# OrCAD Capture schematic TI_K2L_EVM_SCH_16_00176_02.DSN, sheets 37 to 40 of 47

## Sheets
37 PAGE32 : K2L_POWER_SEQUENCING: size C; title: SOC Temp, UCD9090, PMBus Pgm conn, VID Isolator for PMBus
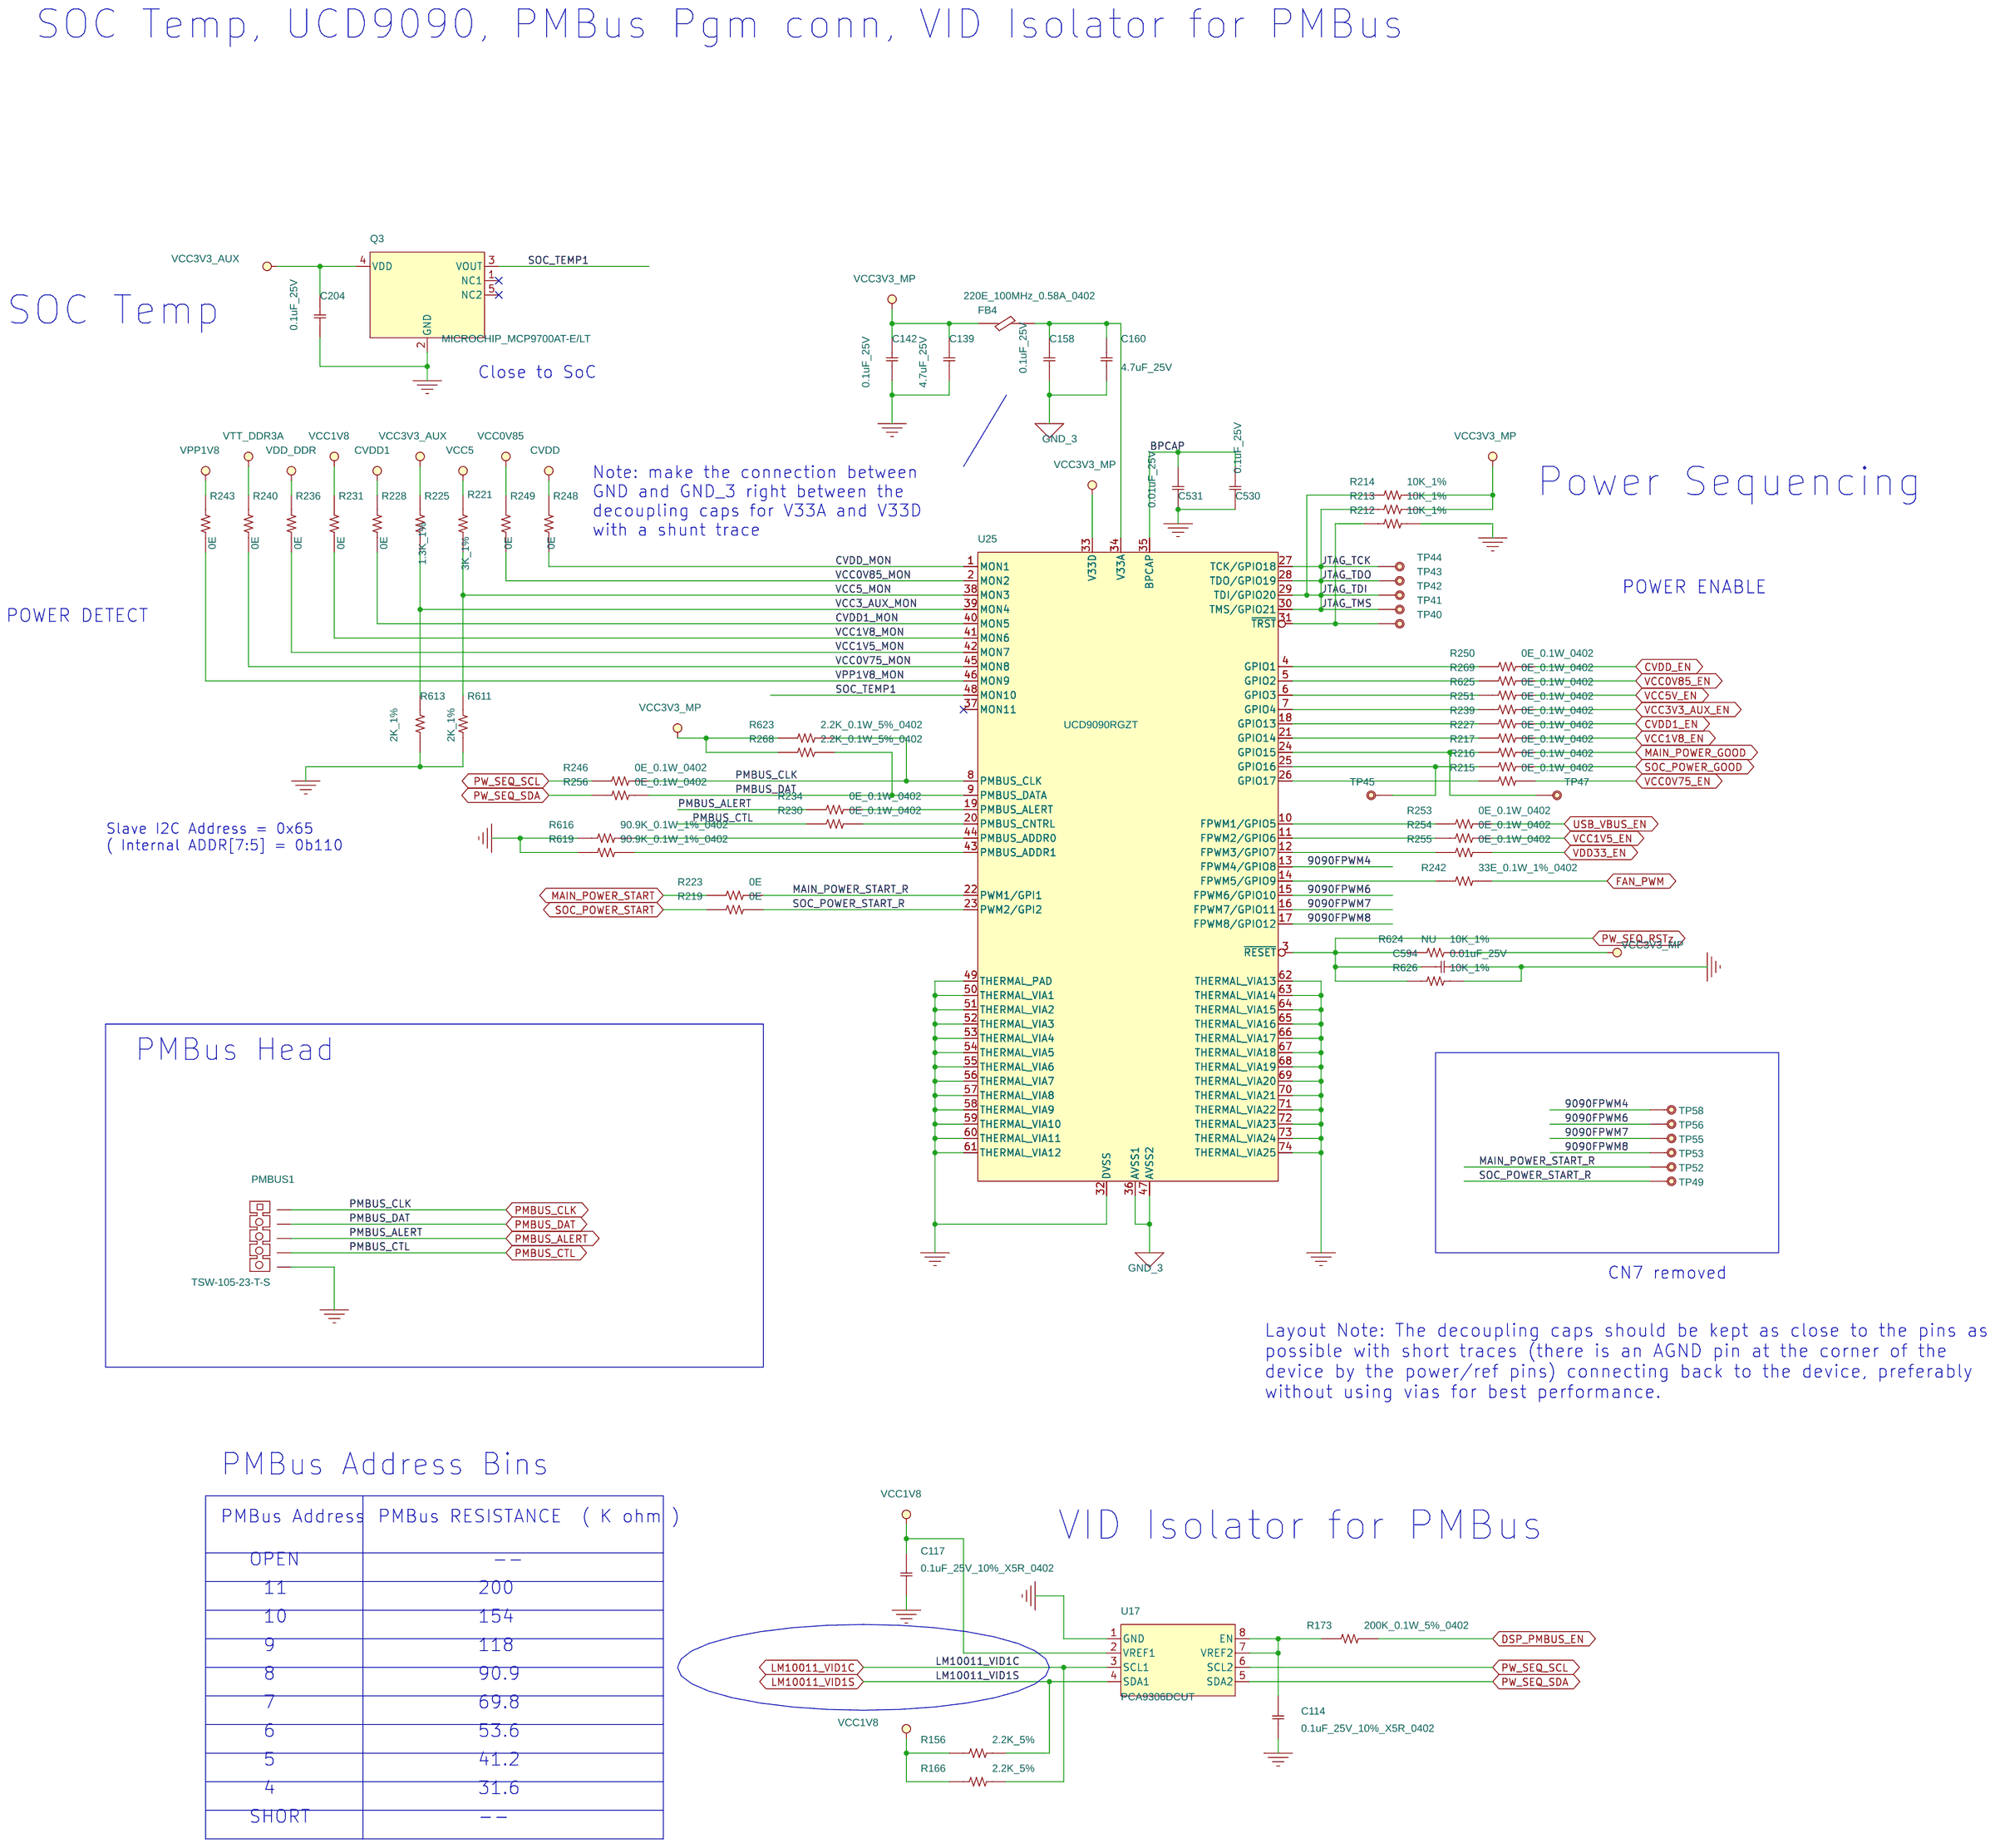
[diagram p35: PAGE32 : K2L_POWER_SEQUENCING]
38 PAGE08 : CLOCK DISTRIBUTION_C: title: CLOCK DISTRIBUTION
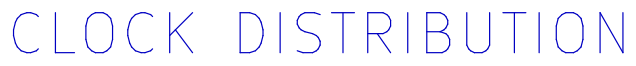
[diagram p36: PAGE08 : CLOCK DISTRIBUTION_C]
39 PAGE07 : POWER DISTRIBUTION_C: title: POWER DISTRIBUTION
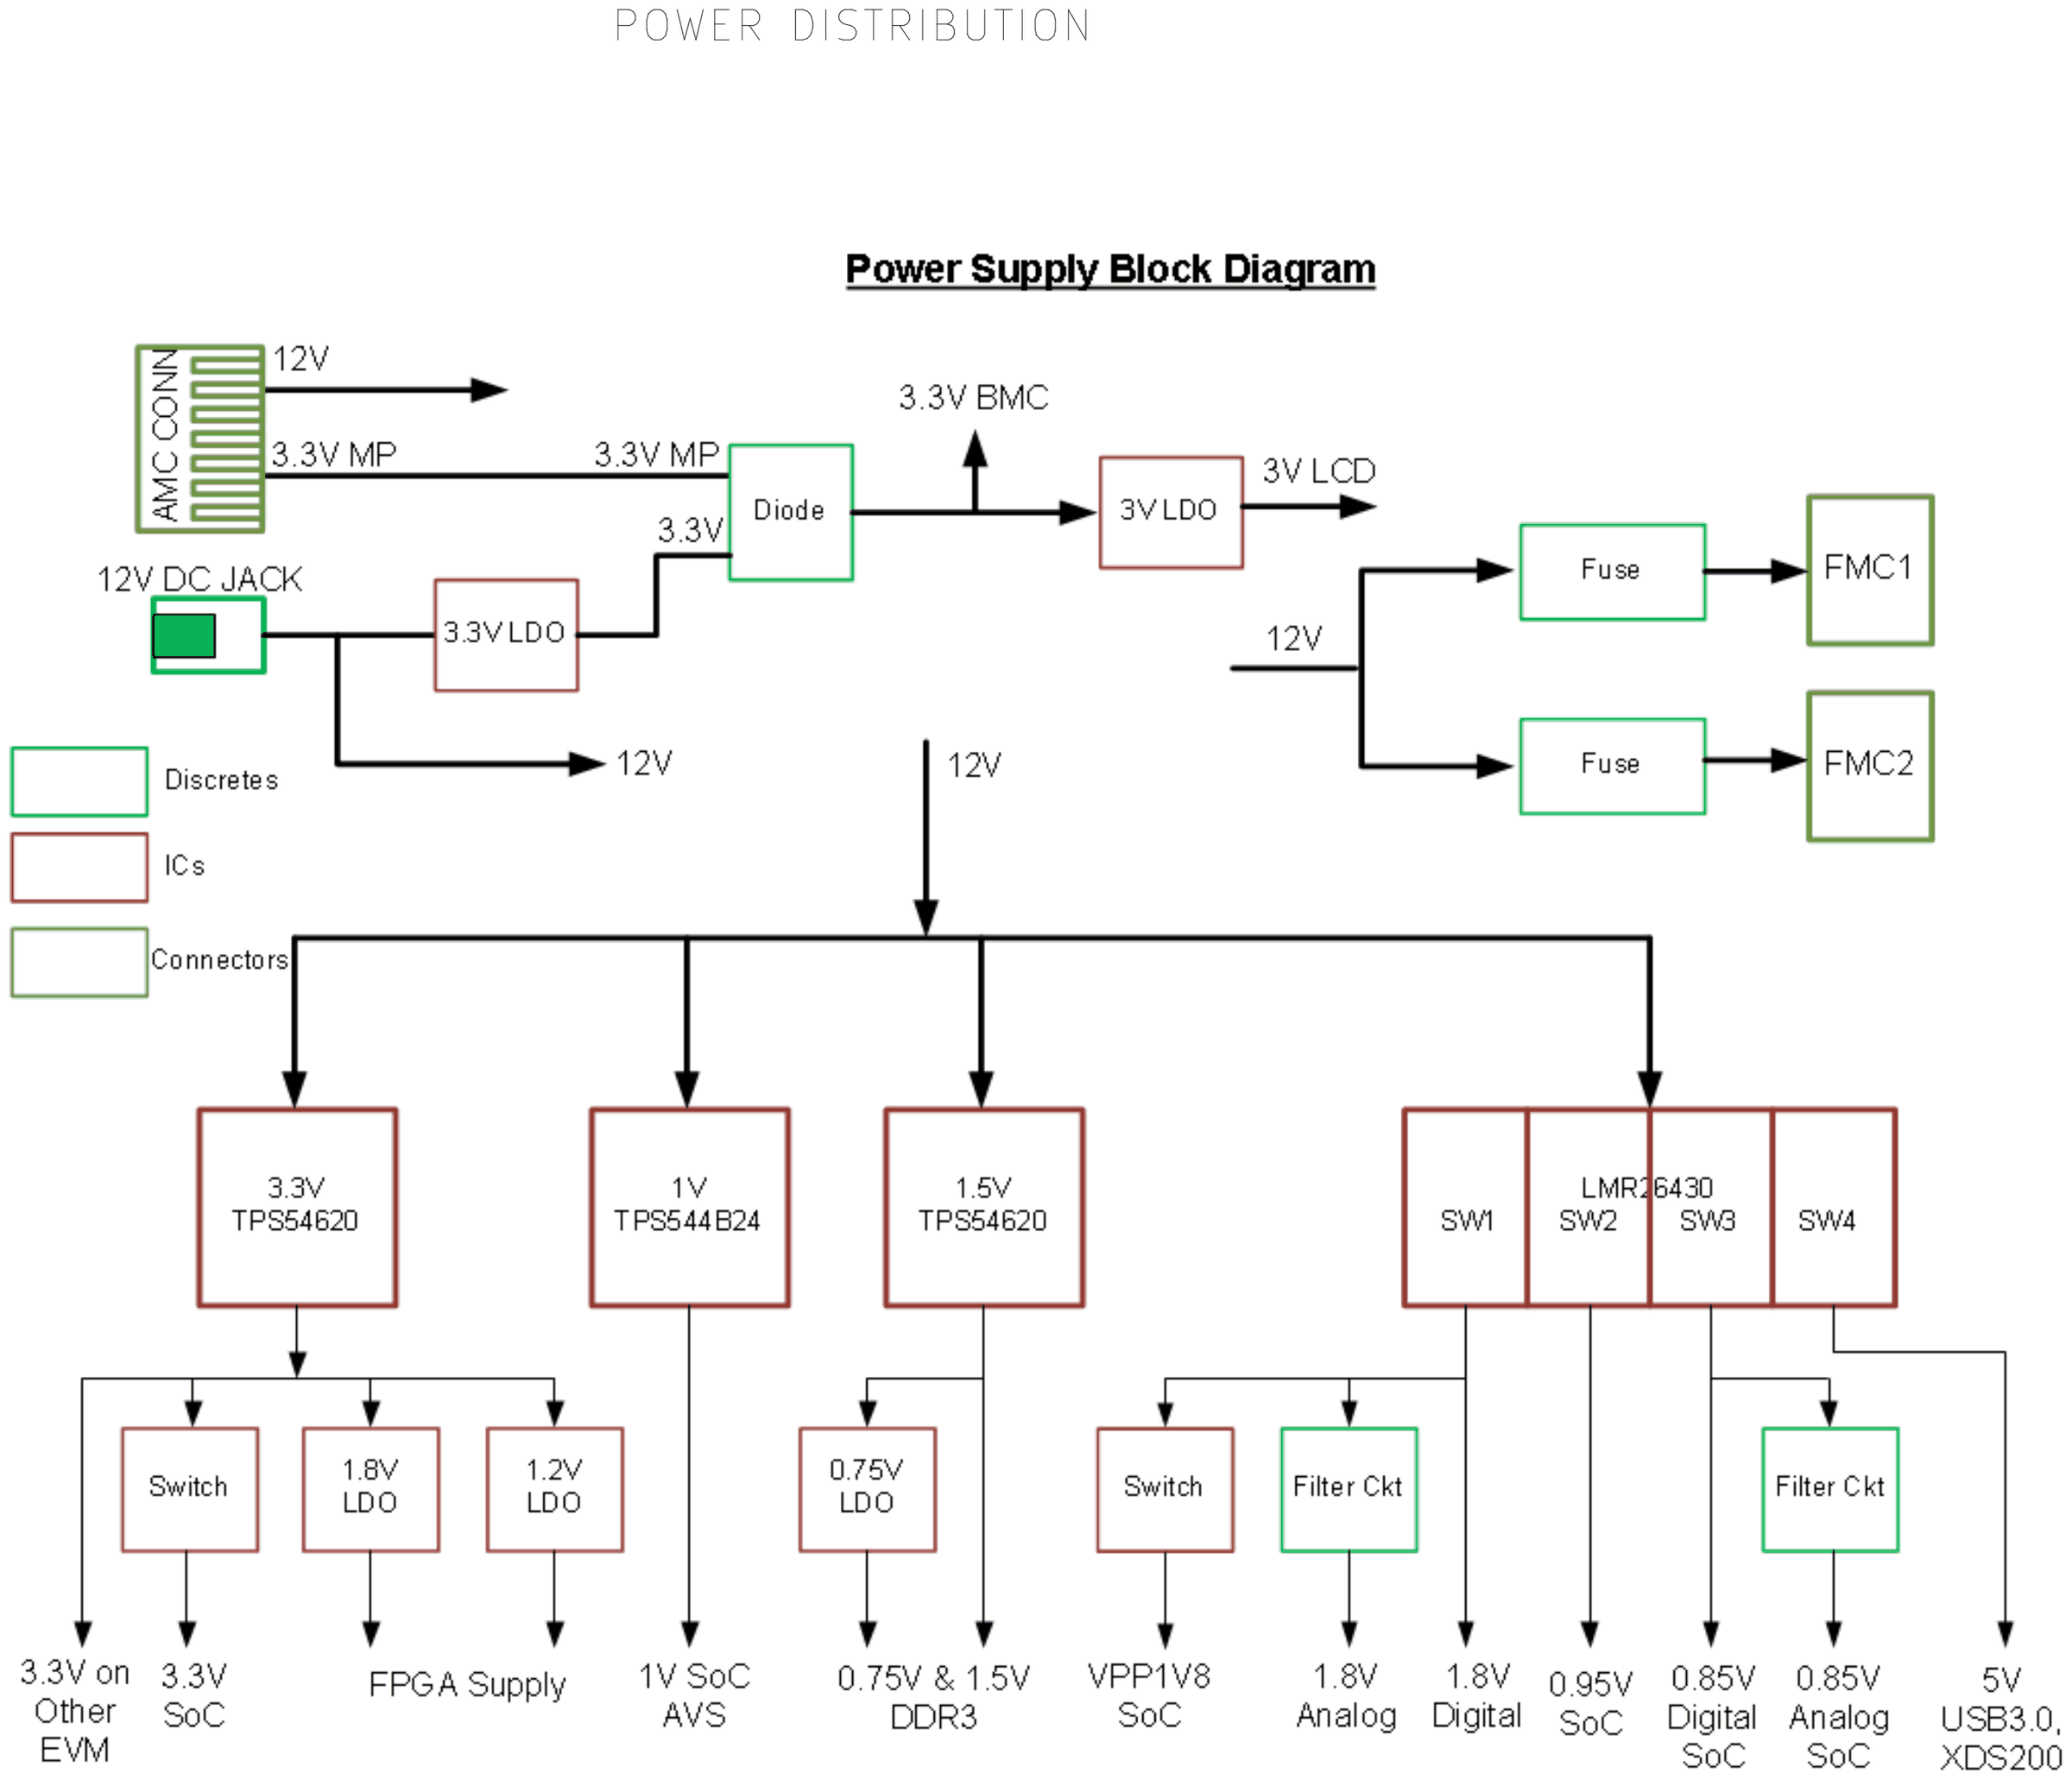
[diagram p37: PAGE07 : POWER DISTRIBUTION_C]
40 PAGE14 : SGMII/PCIe Serdes SW: size C; title: SGMII/PCIe Serdes switch
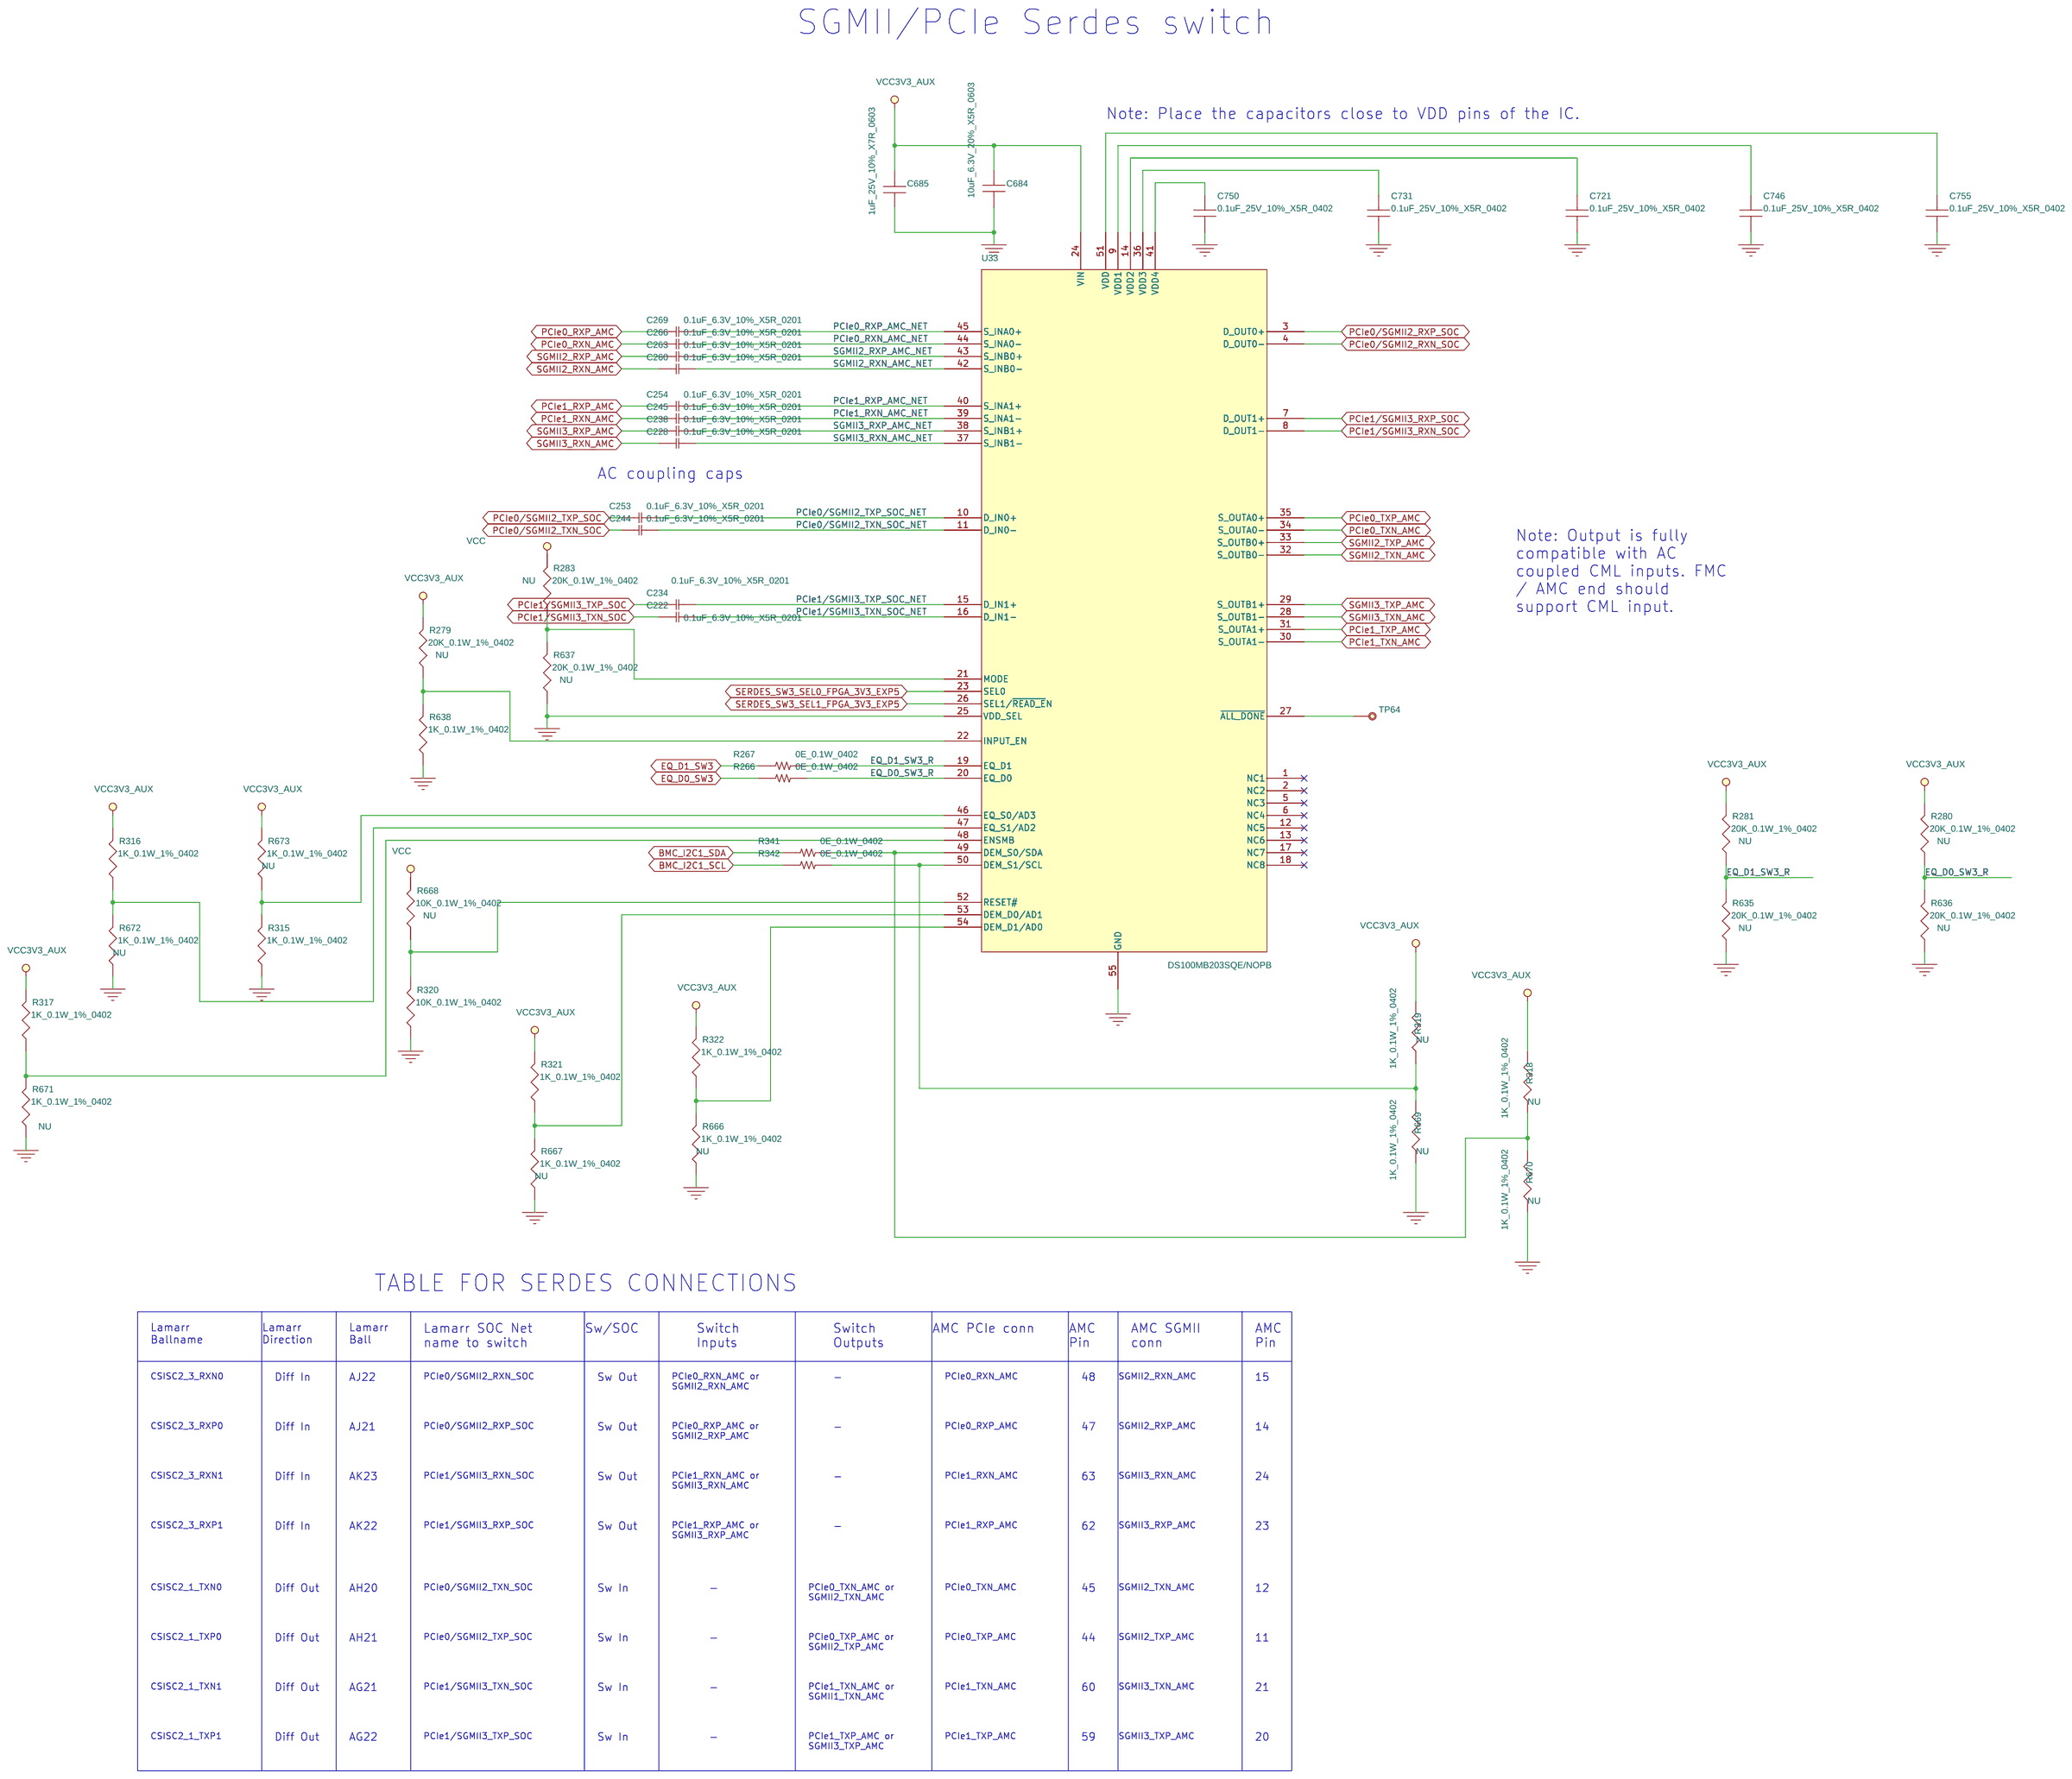
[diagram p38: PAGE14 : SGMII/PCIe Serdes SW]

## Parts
sheet PAGE14 : SGMII/PCIe Serdes SW
C222  0.1uF_6.3V_10%_X5R_0201  [CC0201]
C228  0.1uF_6.3V_10%_X5R_0201  [CC0201]
C234  0.1uF_6.3V_10%_X5R_0201  [CC0201]
C238  0.1uF_6.3V_10%_X5R_0201  [CC0201]
C244  0.1uF_6.3V_10%_X5R_0201  [CC0201]
C245  0.1uF_6.3V_10%_X5R_0201  [CC0201]
C253  0.1uF_6.3V_10%_X5R_0201  [CC0201]
C254  0.1uF_6.3V_10%_X5R_0201  [CC0201]
C260  0.1uF_6.3V_10%_X5R_0201  [CC0201]
C263  0.1uF_6.3V_10%_X5R_0201  [CC0201]
C266  0.1uF_6.3V_10%_X5R_0201  [CC0201]
C269  0.1uF_6.3V_10%_X5R_0201  [CC0201]
C684  10uF_6.3V_20%_X5R_0603  [C0603]
C685  1uF_25V_10%_X7R_0603  [C0603]
C721  0.1uF_25V_10%_X5R_0402  [C0402]
C731  0.1uF_25V_10%_X5R_0402  [C0402]
C746  0.1uF_25V_10%_X5R_0402  [C0402]
C750  0.1uF_25V_10%_X5R_0402  [C0402]
C755  0.1uF_25V_10%_X5R_0402  [C0402]
R266  0E_0.1W_0402  [R0402]
R267  0E_0.1W_0402  [R0402]
R279  20K_0.1W_1%_0402  [RC0402]
R280  20K_0.1W_1%_0402  [RC0402]
R281  20K_0.1W_1%_0402  [RC0402]
R283  20K_0.1W_1%_0402  [RC0402]
R315  1K_0.1W_1%_0402  [R0402]
R316  1K_0.1W_1%_0402  [R0402]
R317  1K_0.1W_1%_0402  [R0402]
R318  1K_0.1W_1%_0402  [R0402]
R319  1K_0.1W_1%_0402  [R0402]
R320  10K_0.1W_1%_0402  [R0402]
R321  1K_0.1W_1%_0402  [R0402]
R322  1K_0.1W_1%_0402  [R0402]
R341  0E_0.1W_0402  [R0402]
R342  0E_0.1W_0402  [R0402]
R635  20K_0.1W_1%_0402  [RC0402]
R636  20K_0.1W_1%_0402  [RC0402]
R637  20K_0.1W_1%_0402  [RC0402]
R638  1K_0.1W_1%_0402  [R0402]
R666  1K_0.1W_1%_0402  [R0402]
R667  1K_0.1W_1%_0402  [R0402]
R668  10K_0.1W_1%_0402  [R0402]
R669  1K_0.1W_1%_0402  [R0402]
R670  1K_0.1W_1%_0402  [R0402]
R671  1K_0.1W_1%_0402  [R0402]
R672  1K_0.1W_1%_0402  [R0402]
R673  1K_0.1W_1%_0402  [R0402]
TP64  TP  [TP-S40]
U33  DS100MB203SQE/NOPB  [QFN50P550X1000X80-55N_EINF]
sheet PAGE32 : K2L_POWER_SEQUENCING
C114  0.1uF_25V_10%_X5R_0402  [C0402]
C117  0.1uF_25V_10%_X5R_0402  [C0402]
C139  4.7uF_25V  [C0603]
C142  0.1uF_25V  [C0402]
C158  0.1uF_25V  [C0402]
C160  4.7uF_25V  [C0603]
C204  0.1uF_25V  [C0402]
C530  0.1uF_25V  [C0402]
C531  0.01uF_25V  [C0402]
C594  0.01uF_25V  [C0402]
FB4  220E_100MHz_0.58A_0402  [L0402]
PMBUS1  TSW-105-23-T-S  [HD_5x1P_100_D]
Q3  MICROCHIP_MCP9700AT-E/LT  [SC-70_5P]
R156  2.2K_5%  [R0402]
R166  2.2K_5%  [R0402]
R173  200K_0.1W_5%_0402  [R0402]
R212  10K_1%  [R0402]
R213  10K_1%  [R0402]
R214  10K_1%  [R0402]
R215  0E_0.1W_0402  [R0402]
R216  0E_0.1W_0402  [R0402]
R217  0E_0.1W_0402  [R0402]
R219  0E  [R0402]
R221  3K_1%  [R0402]
R223  0E  [R0402]
R225  1.3K_1%  [R0402]
R227  0E_0.1W_0402  [R0402]
R228  0E  [R0402]
R230  0E_0.1W_0402  [R0402]
R231  0E  [R0402]
R234  0E_0.1W_0402  [R0402]
R236  0E  [R0402]
R239  0E_0.1W_0402  [R0402]
R240  0E  [R0402]
R242  33E_0.1W_1%_0402  [R0402]
R243  0E  [R0402]
R246  0E_0.1W_0402  [R0402]
R248  0E  [R0402]
R249  0E  [R0402]
R250  0E_0.1W_0402  [R0402]
R251  0E_0.1W_0402  [R0402]
R253  0E_0.1W_0402  [R0402]
R254  0E_0.1W_0402  [R0402]
R255  0E_0.1W_0402  [R0402]
R256  0E_0.1W_0402  [R0402]
R268  2.2K_0.1W_5%_0402  [R0402]
R269  0E_0.1W_0402  [R0402]
R611  2K_1%  [R0402]
R613  2K_1%  [R0402]
R616  90.9K_0.1W_1%_0402  [R0402]
R619  90.9K_0.1W_1%_0402  [R0402]
R623  2.2K_0.1W_5%_0402  [R0402]
R624  10K_1%  [R0402]
R625  0E_0.1W_0402  [R0402]
R626  10K_1%  [R0402]
TP40  TP  [TP-S40]
TP41  TP  [TP-S40]
TP42  TP  [TP-S40]
TP43  TP  [TP-S40]
TP44  TP  [TP-S40]
TP45  TP  [TP-S40]
TP47  TP  [TP-S40]
TP49  TP  [TP-S40]
TP52  TP  [TP-S40]
TP53  TP  [TP-S40]
TP55  TP  [TP-S40]
TP56  TP  [TP-S40]
TP58  TP  [TP-S40]
U17  PCA9306DCUT  [SOIC_8P_20_79X122]
U25  UCD9090RGZT  [QFN_48P_20_276x276_TP202V25]

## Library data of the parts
C222 C228 C234 C238 C244 C245 C253 C254 C260 C263 C266 C269 = 11_C_12: CAP CER 0.1UF 6.3V 10% X5R 0201; Alt Mfg: Taiyo Yuden; Alt Mfg Part#: TMK105BJ104KV-F; Characteristic: <Characteristic>; Distributor_name: DIGIKEY; Distributor_part_number: 445-1796-1-ND; EIC Part#: 03_00583_01; Manufacture: TDK Corporation; Manufacture Part Number: C0603X5R0J104K030BC; Manufacture(English): TDK Corporation; Manufacture_Part_Number: C0603X5R0J104K030BC; Manufacturer: TDK Corporation; Manufacturer_Part_No: C0603X5R0J104K030BC; Mfg: TDK Corporation; Mfg Part#: 03_00583_01; Mfr_name: TDK Corporation; Mfr_part_number: C0603X5R0J104K030BC; Oper. Temp. Range: -55°C ~ 85°C; Package: 0201; Price @ 1: 0.10000; Price @ 10K: 0.00675; Price @ 1K: 0.00810; ProcessType: SMT; RoHS: Yes; Tolerance: 10%; Vendor: DIGIKEY; Vendor Part#: 445-1796-2-ND; Vendor_Part_No: 445-1796-1-ND; Voltage: 6.3V; eI Part#: 03_00583_01
C684 = CAP: CAP CER 10UF 6.3V 20% X5R 0603; Distributor_name: DIGIKEY; Distributor_part_number: 587-3383-1-ND; EIC Part#: 03_00605_01; Manufacture: Taiyo Yuden; Manufacture Part Number: JMK107ABJ106MAHT; Manufacture(English): Taiyo Yuden; Manufacture_Part_Number: JMK107ABJ106MAHT; Manufacturer: Taiyo Yuden; Manufacturer_Part_No: JMK107ABJ106MAHT; Mfg: Taiyo Yuden; Mfg Part#: JMK107ABJ106MAHT; Mfr_name: Taiyo Yuden; Mfr_part_number: JMK107ABJ106MAHT; Price @ 1: 0.44000; Price @ 10K: 0.06105; Price @ 1K: 0.12650; Vendor: DIGIKEY; Vendor_Part_No: 587-3383-1-ND; eI Part#: 03_00605_01
C685 = CAP: CAP CER 1UF 25V 10% X5R 0603; Distributor_name: DIGIKEY; Distributor_part_number: 490-3897-1-ND; EIC Part#: 03_00161_02; Manufacture: Murata; Manufacture Part Number: GRM188R61E105KA12D; Manufacture(English): Murata; Manufacture_Part_Number: GRM188R71E105KA12D; Manufacturer: Murata; Manufacturer_Part_No: GRM188R61E105KA12D; Mfg: Murata; Mfg Part#: 03_00161_02; Mfr_name: Murata; Mfr_part_number: GRM188R61E105KA12D; Price @ 1: 0.38000; Price @ 10K: 0.07363; Price @ 1K: 0.09353; Vendor: DIGIKEY; Vendor_Part_No: 490-3897-1-ND; eI Part#: 03_00161_02
C721 C731 C746 C750 C755 = CAP: CAP CER 0.1UF 25V 10% X5R 0402; Distributor_name: DIGIKEY; Distributor_part_number: 445-4964-1-ND; EIC Part#: 03_00470_02; Manufacture: TDK Corporation; Manufacture Part Number: C1005X5R1E104K050BC; Manufacture(English): TDK Corporation; Manufacture_Part_Number: GRM155R61E104KA87D; Manufacturer: TDK Corporation; Manufacturer_Part_No: C1005X5R1E104K050BC; Mfg: Murata Electronics North America; Mfg Part#: 03_00470_02; Mfr_name: TDK Corporation; Mfr_part_number: C1005X5R1E104K050BC; Price @ 1: 0.10000; Price @ 1K: 0.00960; Vendor: DIGIKEY; Vendor Part#: 445-4964-1-ND; Vendor_Part_No: 445-4964-1-ND; eI Part#: 03_00470_02
R266 R267 R341 R342 = 10_R_0: RES 0.0 OHM 1/10W JUMP 0402 SMD; Distributor_name: DIGIKEY; Distributor_part_number: P0.0JCT-ND; EIC Part#: 02_00019_01; Manufacture: Panasonic - ECG; Manufacture Part Number: ERJ-2GE0R00X; Manufacture(English): Panasonic - ECG; Manufacture_Part_Number: ERJ-2GE0R00X; Manufacturer: Panasonic - ECG; Manufacturer_Part_No: ERJ-2GE0R00X; Mfg: PANASONIC ELECTRONIC COMPONENTS (VA); Mfg Part#: 02_00019_01; Mfr_name: Panasonic - ECG; Mfr_part_number: ERJ-2GE0R00X; Price @ 1: 0.05000; Price @ 10K: 0.00248; Price @ 1K: 0.00480; Vendor: DIGIKEY; Vendor_Part_No: P0.0JCT-ND; eI Part#: 02_00019_01
R279 = DISC_RESISTOR: RES 20.0K OHM 1/10W 1% 0402 SMD; Distributor_name: DIGIKEY; Distributor_part_number: P20.0KLCT-ND; EIC Part#: 02_00037_01; Manufacture: Panasonic - ECG; Manufacture Part Number: ERJ-2RKF2002X; Manufacture(English): Panasonic - ECG; Manufacture_Part_Number: ERJ-2RKF2002X; Manufacturer: Panasonic - ECG; Manufacturer_Part_No: ERJ-2RKF2002X; Mfg Part#: 02_00037_01; Mfr_name: Panasonic - ECG; Mfr_part_number: ERJ-2RKF2002X; Mounting Status: NU; Mounting_Status: NU; Price @ 1: 0.10000; Price @ 10K: 0.00347; Price @ 1K: 0.00672; Vendor: DIGIKEY; Vendor_Part_No: P20.0KLCT-ND; eI Part#: 02_00045_01
R280 = DISC_RESISTOR: RES 20.0K OHM 1/10W 1% 0402 SMD; Distributor_name: DIGIKEY; Distributor_part_number: P20.0KLCT-ND; EIC Part#: 02_00037_01; Manufacture: Panasonic - ECG; Manufacture Part Number: ERJ-2RKF2002X; Manufacture(English): Panasonic - ECG; Manufacture_Part_Number: ERJ-2RKF2002X; Manufacturer: Panasonic - ECG; Manufacturer_Part_No: ERJ-2RKF2002X; Mfg Part#: 02_00037_01; Mfr_name: Panasonic - ECG; Mfr_part_number: ERJ-2RKF2002X; Mounting Status: NU; Mounting_Status: NU; Price @ 1: 0.10000; Price @ 10K: 0.00347; Price @ 1K: 0.00672; Vendor: DIGIKEY; Vendor_Part_No: P20.0KLCT-ND; eI Part#: 02_00247_01
R281 R637 = DISC_RESISTOR: RES 20.0K OHM 1/10W 1% 0402 SMD; Distributor_name: DIGIKEY; Distributor_part_number: P20.0KLCT-ND; EIC Part#: 02_00037_01; Manufacture: Panasonic - ECG; Manufacture Part Number: ERJ-2RKF2002X; Manufacture(English): Panasonic - ECG; Manufacture_Part_Number: ERJ-2RKF2002X; Manufacturer: Panasonic - ECG; Manufacturer_Part_No: ERJ-2RKF2002X; Mfg Part#: 02_00037_01; Mfr_name: Panasonic - ECG; Mfr_part_number: ERJ-2RKF2002X; Mounting Status: NU; Mounting_Status: NU; Price @ 1: 0.10000; Price @ 10K: 0.00347; Price @ 1K: 0.00672; Vendor: DIGIKEY; Vendor_Part_No: P20.0KLCT-ND; eI Part#: 02_00019_01
R283 = DISC_RESISTOR: RES 20.0K OHM 1/10W 1% 0402 SMD; Distributor_name: DIGIKEY; Distributor_part_number: P20.0KLCT-ND; EIC Part#: 02_00037_01; Manufacture: Panasonic - ECG; Manufacture Part Number: ERJ-2RKF2002X; Manufacture(English): Panasonic - ECG; Manufacture_Part_Number: ERJ-2RKF2002X; Manufacturer: Panasonic - ECG; Manufacturer_Part_No: ERJ-2RKF2002X; Mfg Part#: 02_00037_01; Mfr_name: Panasonic - ECG; Mfr_part_number: ERJ-2RKF2002X; Mounting Status: NU; Mounting_Status: NU; Price @ 1: 0.10000; Price @ 10K: 0.00347; Price @ 1K: 0.00672; Vendor: DIGIKEY; Vendor_Part_No: P20.0KLCT-ND; eI Part#: 02_00037_01
R315-R317 R321 R322 R638 = DISC_RESISTOR: RES 1.00K OHM 1/10W 1% 0402 SMD; Distributor_name: DIGIKEY; Distributor_part_number: P1.00KLCT-ND; EIC Part#: 02_00045_01; Manufacture: Panasonic - ECG; Manufacture Part Number: ERJ-2RKF1001X; Manufacture(English): Panasonic - ECG; Manufacture_Part_Number: ERJ-2RKF1001X; Manufacturer: Panasonic - ECG; Manufacturer_Part_No: ERJ-2RKF1001X; Mfg Part#: 02_00045_01; Mfr_name: Panasonic - ECG; Mfr_part_number: ERJ-2RKF1001X; Price @ 1: 0.10000; Price @ 10K: 0.00347; Price @ 1K: 0.00672; Vendor: DIGIKEY; Vendor_Part_No: P1.00KLCT-ND; eI Part#: 02_00045_01
R318 R319 R669 R670 = RESISTOR: RES 1.00K OHM 1/10W 1% 0402 SMD; Distributor_name: DIGIKEY; Distributor_part_number: P1.00KLCT-ND; EI Part#: 02_00045_01; EIC Part#: 02_00045_01; Manufacture: Panasonic - ECG; Manufacture Part Number: ERJ-2RKF1001X; Manufacture(English): Panasonic - ECG; Manufacture_Part_Number: ERJ-2RKF1001X; Manufacturer: Panasonic - ECG; Manufacturer_Part_No: ERJ-2RKF1001X; Mfg Part#: 02_00045_01; Mfr_name: Panasonic - ECG; Mfr_part_number: ERJ-2RKF1001X; Mounting Status: NU; Mounting_Status: NU; Price @ 1: 0.10000; Price @ 10K: 0.00347; Price @ 1K: 0.00672; Vendor: DIGIKEY; Vendor_Part_No: P1.00KLCT-ND
R320 = DISC_RESISTOR: RES 10K OHM 1/10W 1% 0402 SMD; Distributor_name: DIGIKEY; Distributor_part_number: P10.0KLCT-ND; EIC Part#: 02_00027_01; Manufacture: Panasonic - ECG; Manufacture Part Number: ERJ-2RKF1002X; Manufacture(English): Panasonic - ECG; Manufacture_Part_Number: ERJ-2RKF1002X; Manufacturer: Panasonic - ECG; Manufacturer_Part_No: ERJ-2RKF1002X; Mfg Part#: 02_00027_01; Mfr_name: Panasonic - ECG; Mfr_part_number: ERJ-2RKF1002X; Package: 0402; Price @ 1: 0.10000; Price @ 10K: 0.00347; Price @ 1K: 0.00672; Vendor: DIGIKEY; Vendor_Part_No: P10.0KLCT-ND; eI Part#: 02_00027_01
R635 = DISC_RESISTOR: RES 20.0K OHM 1/10W 1% 0402 SMD; Distributor_name: DIGIKEY; Distributor_part_number: P20.0KLCT-ND; EIC Part#: 02_00037_01; Manufacture: Panasonic - ECG; Manufacture Part Number: ERJ-2RKF2002X; Manufacture(English): Panasonic - ECG; Manufacture_Part_Number: ERJ-2RKF2002X; Manufacturer: Panasonic - ECG; Manufacturer_Part_No: ERJ-2RKF2002X; Mfg Part#: 02_00037_01; Mfr_name: Panasonic - ECG; Mfr_part_number: ERJ-2RKF2002X; Mounting Status: NU; Mounting_Status: NU; Price @ 1: 0.10000; Price @ 10K: 0.00347; Price @ 1K: 0.00672; Vendor: DIGIKEY; Vendor_Part_No: P20.0KLCT-ND; eI Part#: 02_00043_02
R636 = DISC_RESISTOR: RES 20.0K OHM 1/10W 1% 0402 SMD; Distributor_name: DIGIKEY; Distributor_part_number: P20.0KLCT-ND; EIC Part#: 02_00037_01; Manufacture: Panasonic - ECG; Manufacture Part Number: ERJ-2RKF2002X; Manufacture(English): Panasonic - ECG; Manufacture_Part_Number: ERJ-2RKF2002X; Manufacturer: Panasonic - ECG; Manufacturer_Part_No: ERJ-2RKF2002X; Mfg Part#: 02_00037_01; Mfr_name: Panasonic - ECG; Mfr_part_number: ERJ-2RKF2002X; Mounting Status: NU; Mounting_Status: NU; Price @ 1: 0.10000; Price @ 10K: 0.00347; Price @ 1K: 0.00672; Vendor: DIGIKEY; Vendor_Part_No: P20.0KLCT-ND; eI Part#: 02_00025_01
R666 R667 R671-R673 = DISC_RESISTOR: RES 1.00K OHM 1/10W 1% 0402 SMD; Distributor_name: DIGIKEY; Distributor_part_number: P1.00KLCT-ND; EIC Part#: 02_00045_01; Manufacture: Panasonic - ECG; Manufacture Part Number: ERJ-2RKF1001X; Manufacture(English): Panasonic - ECG; Manufacture_Part_Number: ERJ-2RKF1001X; Manufacturer: Panasonic - ECG; Manufacturer_Part_No: ERJ-2RKF1001X; Mfg Part#: 02_00045_01; Mfr_name: Panasonic - ECG; Mfr_part_number: ERJ-2RKF1001X; Mounting Status: NU; Mounting_Status: NU; Price @ 1: 0.10000; Price @ 10K: 0.00347; Price @ 1K: 0.00672; Vendor: DIGIKEY; Vendor_Part_No: P1.00KLCT-ND; eI Part#: 02_00045_01
R668 = DISC_RESISTOR: RES 10K OHM 1/10W 1% 0402 SMD; Distributor_name: DIGIKEY; Distributor_part_number: P10.0KLCT-ND; EIC Part#: 02_00027_01; Manufacture: Panasonic - ECG; Manufacture Part Number: ERJ-2RKF1002X; Manufacture(English): Panasonic - ECG; Manufacture_Part_Number: ERJ-2RKF1002X; Manufacturer: Panasonic - ECG; Manufacturer_Part_No: ERJ-2RKF1002X; Mfg Part#: 02_00027_01; Mfr_name: Panasonic - ECG; Mfr_part_number: ERJ-2RKF1002X; Mounting: NU; Mounting Status: NU; Mounting_Status: NU; Package: 0402; Price @ 1: 0.10000; Price @ 10K: 0.00347; Price @ 1K: 0.00672; Vendor: DIGIKEY; Vendor_Part_No: P10.0KLCT-ND; eI Part#: 02_00027_01
TP64 = 00_TP-S40_0: TEST PAD TP; Distributor_name: NA; Distributor_part_number: NA; EIC Part#: NA; Manufacture: NA; Manufacture Part Number: NA; Manufacture(English): NA; Manufacture_Part_Number: NA; Manufacturer: NA; Manufacturer_Part_No: NA; Mfg: NA; Mfg Part#: NA; Mfr_name: NA; Mfr_part_number: NA; Oper. Temp. Range: --NA--; Package: --NA--; Price @ 1: NA; Price @ 10K: NA; Price @ 1K: NA; ProcessType: SMT; RoHS: Yes; Vendor: NA; Vendor Part#: --NA--; Vendor_Part_No: NA; eI Part#: NA
U33 = DS100MB203SQE: IC MUX/BUFFER DUAL PORT 54WQF; Distributor_name: DIGIKEY; Distributor_part_number: DS100MB203SQE/NOPB-ND; EIC Part#: TBD; Manufacture: TI; Manufacture(English): TI; Manufacturer: TI; Mfg: TI; Mfg Part#: TBD; Mfr_name: TI; Price @ 10K: 14.33300; Price @ 1K: 14.33300; Vendor: DIGIKEY; Vendor_Part_No: DS100MB203SQE/NOPB-ND; eI Part#: 01_01136_01
C114 = 11_C_12: CAP CER 0.1UF 25V 10% X5R 0402; Alt Mfg: Taiyo Yuden; Distributor_name: DIGIKEY; Distributor_part_number: 445-4964-1-ND; EIC Part#: 03_00470_02; MOUNTED: <MOUNTED>; Manufacture: TDK Corporation; Manufacture Part Number: C1005X5R1E104K050BC; Manufacture(English): TDK Corporation; Manufacture_Part_Number: GRM155R61E104KA87D; Manufacturer: TDK Corporation; Manufacturer_Part_No: C1005X5R1E104K050BC; Mfg: Murata Electronics North America; Mfg Part#: 03_00470_02; Mfr_name: TDK Corporation; Mfr_part_number: C1005X5R1E104K050BC; Oper. Temp. Range: -55°C ~ 85°C; Package: 0402; Price @ 1: 0.10000; Price @ 1K: 0.00960; ProcessType: SMT; RoHS: Yes; Tolerance: 10%; Vendor: DIGIKEY; Vendor Part#: 445-4964-1-ND; Vendor_Part_No: 445-4964-1-ND; eI Part#: 03_00470_02
C117 = 11_C_12: CAP CER 0.1UF 25V 10% X5R 0402; Alt Mfg: Taiyo Yuden; Distributor_name: DIGIKEY; Distributor_part_number: 445-4964-1-ND; EIC Part#: 03_00470_02; MOUNTED: <MOUNTED>; Manufacture: TDK Corporation; Manufacture Part Number: C1005X5R1E104K050BC; Manufacture(English): TDK Corporation; Manufacture_Part_Number: GRM155R61E104KA87D; Manufacturer: TDK Corporation; Manufacturer_Part_No: C1005X5R1E104K050BC; Mfg: Murata Electronics North America; Mfg Part#: 03_00470_02; Mfr_name: TDK Corporation; Mfr_part_number: C1005X5R1E104K050BC; Oper. Temp. Range: -55C to 85C; Package: 0402; Price @ 1: 0.10000; Price @ 1K: 0.00960; ProcessType: SMT; RoHS: Yes; Tolerance: 10%; Vendor: DIGIKEY; Vendor Part#: 445-4964-1-ND; Vendor_Part_No: 445-4964-1-ND; eI Part#: 03_00470_02
C139 C160 = 11_C_12: CAP CER 4.7UF 25V 20% X5R 0603; Characteristic: <Characteristic>; Distributor_name: DIGIKEY; Distributor_part_number: 1276-1903-2-ND; EIC Part#: 03_00592_01; Manufacture: Samsung; Manufacture Part Number: CL10A475MA8NQNC; Manufacture(English): Samsung; Manufacture_Part_Number: CL10A475MA8NQNC; Manufacturer: Samsung; Manufacturer_Part_No: CL10A475MA8NQNC; Mfg: Samsung; Mfg Part#: CL10A475MA8NQNC; Mfr_name: Samsung; Mfr_part_number: CL10A475MA8NQNC; Oper. Temp. Range: -55C to 85C; Package: 0603; Price @ 1: 0.16000; Price @ 10K: 0.02322; Price @ 1K: 0.02970; ProcessType: SMT; RoHS: Yes; Tolerance: 10%; Vendor: DIGIKEY; Vendor Part#: 1276-1903-2-ND; Vendor_Part_No: 1276-1903-2-ND; Voltage: 6.3V; eI Part#: 03_00592_01
C142 C158 C204 C530 = 11_C_12: CAP CER 0.1UF 25V 10% X5R 0402; Alt Mfg: Taiyo Yuden; Distributor_name: DIGIKEY; Distributor_part_number: 445-4964-1-ND; EIC Part#: 03_00470_02; Manufacture: TDK Corporation; Manufacture Part Number: C1005X5R1E104K050BC; Manufacture(English): TDK Corporation; Manufacture_Part_Number: GRM155R61E104KA87D; Manufacturer: TDK Corporation; Manufacturer_Part_No: C1005X5R1E104K050BC; Mfg: Murata Electronics North America; Mfg Part#: 03_00470_02; Mfr_name: TDK Corporation; Mfr_part_number: C1005X5R1E104K050BC; Oper. Temp. Range: -55°C ~ 85°C; Package: 0402; Price @ 1: 0.10000; Price @ 1K: 0.00960; ProcessType: SMT; RoHS: Yes; Tolerance: 10%; Vendor: DIGIKEY; Vendor Part#: 445-4964-1-ND; Vendor_Part_No: 445-4964-1-ND; eI Part#: 03_00470_02
C531 C594 = 11_C_0: CAP CER 10000PF 25V 10% X7R 0402; Alt Mfg: Murata; Alt Mfg Part#: GRM155R71C103KA01D; Distributor_name: DIGIKEY; Distributor_part_number: 445-1260-1-ND; EIC Part#: 03_00029_04; Manufacture: TDK Corporation; Manufacture Part Number: C1005X7R1E103K; Manufacture(English): TDK Corporation; Manufacture_Part_Number: C1005X7R1E103K; Manufacturer: TDK Corporation; Manufacturer_Part_No: C1005X7R1E103K; Mfg: TDK Corporation; Mfg Part#: 03_00029_04; Mfr_name: TDK Corporation; Mfr_part_number: C1005X7R1E103K; Oper. Temp. Range: -55C to 125C; Package: 0402; Price @ 1: 0.10000; Price @ 10K: 0.00420; Price @ 1K: 0.00600; ProcessType: SMT; RoHS: Yes; Tolerance: 10%; Vendor: DIGIKEY; Vendor Part#: PCC103BQCT-ND; Vendor_Part_No: 445-1260-1-ND; Voltage: 16V; eI Part#: 03_00029_04
FB4 = 1212_BEAD_0: FERRITE CHIP 220 OHM 0402; AVL_Part: AVL; Characteristic: 0.58A; Distributor_name: DIGIKEY; Distributor_part_number: 490-5440-1-ND; EIC Part#: TBD; Manufacture: Murata; Manufacture Part Number: BLM15AX221SN1D; Manufacture(English): Murata; Manufacture_Part_Number: BLM15AX221SN1D; Manufacturer: Murata; Manufacturer_Part_No: BLM15AX221SN1D; Mfg: Murata Electronics North America; Mfg Part#: TBD; Mfr_name: Murata; Mfr_part_number: BLM15AX221SN1D; Package: 0402; Part_Number: 1212002796-01; Price @ 1: 0.11000; Price @ 10K: 0.02296; Price @ 1K: 0.02886; ProcessType: SMT; Tolerance: 25%; Vendor: DIGIKEY; Vendor_Part_No: 490-5440-1-ND; eI Part#: TBD
PMBUS1 = 1653_JH5X1V_0: CONN HEADER 5POS .100 SNGL TIN; Advansus_Part_Number: 12G06000005C; Avalue_Part_Number: E1653005100R; Distributor_name: DIGIKEY; Distributor_part_number: SAM1075-05-ND; EIC Part#: 09_00360_01; Manufacture: Samtec Inc; Manufacture(English): Samtec Inc; Manufacturer: Samtec Inc; Mfg: Samtec Inc; Mfg Part#: 09_00360_01; Mfr_name: Samtec Inc; Package: PH5x1P-2.54; Part_Number: 1653005100; Price @ 1: 0.61000; Price @ 10K: 0.26725; Price @ 1K: 0.30467; ProcessType: DIP; Vendor: DIGIKEY; Vendor_Part_No: SAM1075-05-ND; eI Part#: 09_00360_01
Q3 = 141_MICROCHIP_MCP9700AT-E-LT_0: IC SENSOR THERMAL 2.3V SC70-5; Distributor_name: DIGIKEY; Distributor_part_number: MCP9700AT-E/LTCT-ND; EIC Part#: 01_00850_01; Manufacture: Microchip Technology; Manufacture Part Number: MCP9700AT-E/LT; Manufacture(English): Microchip Technology; Manufacture_Part_Number: MCP9700AT-E/LT; Manufacturer: Microchip Technology; Manufacturer_Part_No: MCP9700AT-E/LT; Mfg: Microchip Technology; Mfg Part#: 01_00850_01; Mfr_name: Microchip Technology; Mfr_part_number: MCP9700AT-E/LT; Package: SC70-5; Part_Number: 1410021437; Price @ 1: 0.37000; Price @ 10K: 0.24000; Price @ 1K: 0.24000; ProcessType: SMT; Vendor: DIGIKEY; Vendor_Part_No: MCP9700AT-E/LTCT-ND; eI Part#: 01_00850_01
R156 = 10_R_0: RES 2.2K OHM 1/10W 5% 0402 SMD; Alt Mfg: Yageo; Alt Mfg Part#: RC0402JR-072K2L; Distributor_name: DIGIKEY; Distributor_part_number: P2.2KJCT-ND; EIC Part#: 02_00024_01; Manufacture: Panasonic - ECG; Manufacture Part Number: ERJ-2GEJ222X; Manufacture(English): Panasonic - ECG; Manufacture_Part_Number: ERJ-2GEJ222X; Manufacturer: Panasonic - ECG; Manufacturer_Part_No: ERJ-2GEJ222X; Mfg Part#: 02_00024_01; Mfr_name: Panasonic - ECG; Mfr_part_number: ERJ-2GEJ222X; Oper. Temp. Range: -55C to 125C; Package: 0402; ProcessType: SMT; Remark: Alt part is 1/16W; RoHS: Yes; Specifications: RES 2.2K OHM 1/10W 5% 0402 SMD; Tolerance: 5%; Vendor: DIGIKEY; Vendor Part#: P2.2KJCT-ND; Vendor_Part_No: P2.2KJCT-ND; eI Part#: 02_00027_01
R166 R268 = 10_R_0: RES 2.2K OHM 1/10W 5% 0402 SMD; Alt Mfg: Yageo; Alt Mfg Part#: RC0402JR-072K2L; Distributor_name: DIGIKEY; Distributor_part_number: P2.2KJCT-ND; EIC Part#: 02_00024_01; Manufacture: Panasonic - ECG; Manufacture Part Number: ERJ-2GEJ222X; Manufacture(English): Panasonic - ECG; Manufacture_Part_Number: ERJ-2GEJ222X; Manufacturer: Panasonic - ECG; Manufacturer_Part_No: ERJ-2GEJ222X; Mfg Part#: 02_00024_01; Mfr_name: Panasonic - ECG; Mfr_part_number: ERJ-2GEJ222X; Oper. Temp. Range: -55C to 125C; Package: 0402; ProcessType: SMT; Remark: Alt part is 1/16W; RoHS: Yes; Specifications: RES 2.2K OHM 1/10W 5% 0402 SMD; Tolerance: 5%; Vendor: DIGIKEY; Vendor Part#: P2.2KJCT-ND; Vendor_Part_No: P2.2KJCT-ND; eI Part#: 02_00045_01
R173 = 10_R_0: RES 200K OHM 1/10W 5% 0402 SMD; Alt Mfg: Yageo; Alt Mfg Part#: RC0402JR-074K7L; Distributor_name: DIGIKEY; Distributor_part_number: P200KJCT-ND; EIC Part#: 02_00385_01; Manufacture: Panasonic - ECG; Manufacture Part Number: ERJ-2GEJ204X; Manufacture(English): Panasonic - ECG; Manufacturer: Panasonic - ECG; Manufacturer_Part_No: ERJ-2GEJ204X; Mfg Part#: 02_00385_01; Mfr_name: Panasonic - ECG; Mfr_part_number: ERJ-2GEJ204X; Package: 0402; ProcessType: SMT; Remark: Alt part is 1/16W; RoHS: Yes; Tolerance: 5%; Vendor: DIGIKEY; Vendor_Part_No: P200KJCT-ND; eI Part#: 02_00043_02
R212-R214 = 10_R_0: RES 10K OHM 1/10W 1% 0402 SMD; Alt Mfg: Yageo; Alt Mfg Part#: RC0402FR-0710KL; Distributor_name: DIGIKEY; Distributor_part_number: P10.0KLCT-ND; EIC Part#: 02_00027_01; Manufacture: Panasonic - ECG; Manufacture Part Number: ERJ-2RKF1002X; Manufacture(English): Panasonic - ECG; Manufacture_Part_Number: ERJ-2RKF1002X; Manufacturer: Panasonic - ECG; Manufacturer_Part_No: ERJ-2RKF1002X; Mfg: PANASONIC ELECTRONIC COMPONENTS (VA); Mfg Part#: 02_00027_01; Mfr_name: Panasonic - ECG; Mfr_part_number: ERJ-2RKF1002X; Oper. Temp. Range: -55C ~ 125C; Package: 0402; Price @ 1: 0.10000; Price @ 10K: 0.00347; Price @ 1K: 0.00672; ProcessType: SMT; Remark: Alt part is 1/16W; RoHS: Yes; Tolerance: 1%; Vendor: DIGIKEY; Vendor Part#: P10.0KLCT-ND; Vendor_Part_No: P10.0KLCT-ND; eI Part#: 02_00027_01
R215-R217 R219 R223 R227 R228 R230 R231 R234 R236 R239 R240 R243 R246 R248-R251 R253-R256 R269 R625 = 10_R_0: RES 0.0 OHM 1/10W JUMP 0402 SMD; Alt Mfg: Yageo; Distributor_name: DIGIKEY; Distributor_part_number: P0.0JCT-ND; EIC Part#: 02_00019_01; Manufacture: Panasonic - ECG; Manufacture Part Number: ERJ-2GE0R00X; Manufacture(English): Panasonic - ECG; Manufacture_Part_Number: ERJ-2GE0R00X; Manufacturer: Panasonic - ECG; Manufacturer_Part_No: ERJ-2GE0R00X; Mfg Part#: 02_00019_01; Mfr_name: Panasonic - ECG; Mfr_part_number: ERJ-2GE0R00X; Oper. Temp. Range: -55C to 125C; Package: 0402; ProcessType: SMT; Remark: Alt part is 1/16W; RoHS: Yes; Tolerance: 5%; Vendor: DIGIKEY; Vendor Part#: P0.0JCT-ND; Vendor_Part_No: P0.0JCT-ND; eI Part#: 02_00019_01
R221 = 10_R_0: RES 3K OHM 1/10W 1% 0402 SMD; Characteristic: 1%; Distributor_name: DIGIKEY; Distributor_part_number: P3.00KLCT-ND; EIC Part#: 02_00388_01; Manufacture: Panasonic - ECG; Manufacture Part Number: ERJ-2RKF3001X; Manufacture(English): Panasonic - ECG; Manufacture_Part_Number: ERJ-2RKF3001X; Manufacturer: Panasonic - ECG; Manufacturer_Part_No: ERJ-2RKF3001X; Mfg: Panasonic Electronic Components; Mfg Part#: 02_00388_01; Mfr_name: Panasonic - ECG; Mfr_part_number: ERJ-2RKF3001X; Package: 0402; Part_Number: 1000000859-02; Price @ 1: 0.10000; Price @ 10K: 0.00347; Price @ 1K: 0.00672; ProcessType: SMT; Tolerance: 1%; Vendor: DIGIKEY; Vendor_Part_No: P3.00KLCT-ND; eI Part#: 02_00019_01
R225 = 10_R_0: RES 1.30K OHM 1/16W 1% 0402 SMD; Characteristic: 1%; Distributor_name: DIGIKEY; Distributor_part_number: 541-1.30KLCT-ND; EIC Part#: 02_00894_01; Manufacture: Vishay Dale; Manufacture Part Number: CRCW04021K30FKED; Manufacture(English): Vishay Dale; Manufacture_Part_Number: CRCW04021K30FKED; Manufacturer: Vishay Dale; Manufacturer_Part_No: CRCW04021K30FKED; Mfg: Vishay Dale; Mfg Part#: 02_00894_01; Mfr_name: Vishay Dale; Mfr_part_number: CRCW04021K30FKED; Package: 0402; Part_Number: 1000001932; Price @ 1: 0.08300; Price @ 10K: 0.00540; Price @ 1K: 0.01740; ProcessType: SMT; Tolerance: 1%; Vendor: DIGIKEY; Vendor_Part_No: 541-1.30KLCT-ND; eI Part#: 02_00027_01
R242 = 10_R_0: RES 33 OHM 1/10W 1% 0402 SMD; Alt Mfg: Yageo; Alt Mfg Part#: RC0402FR-0733RL; Distributor_name: DIGIKEY; Distributor_part_number: P33.0LCT-ND; EIC Part#: 02_00018_05; Manufacture: Panasonic - ECG; Manufacture Part Number: ERJ-2RKF33R0X; Manufacture(English): Panasonic - ECG; Manufacture_Part_Number: ERJ-2RKF33R0X; Manufacturer: Panasonic - ECG; Manufacturer_Part_No: ERJ-2RKF33R0X; Mfg: Panasonic Electronic Components; Mfg Part#: 02_00018_05; Mfr_name: Panasonic - ECG; Mfr_part_number: ERJ-2RKF33R0X; Oper. Temp. Range: -55C to 125C; Package: 0402; Price @ 1: 0.10000; Price @ 1K: 0.00672; ProcessType: SMT; Remark: Alt part is 1/16W; RoHS: Yes; Tolerance: 1%; Vendor: DIGIKEY; Vendor Part#: P33.0LCT-ND; Vendor_Part_No: P33.0LCT-ND; eI Part#: 02_00027_01
R611 R613 = 10_R_0: RES 2K OHM 1/10W 1% 0402 SMD; Characteristic: 1%; Distributor_name: DIGIKEY; Distributor_part_number: P2.00KLCT-ND; EIC Part#: 02_00229_02; Manufacture: Panasonic - ECG; Manufacture Part Number: ERJ-2RKF2001X; Manufacture(English): Panasonic - ECG; Manufacture_Part_Number: ERJ-2RKF2001X; Manufacturer: Panasonic - ECG; Manufacturer_Part_No: ERJ-2RKF2001X; Mfg: Panasonic - ECG; Mfg Part#: ERJ-2RKF2001X; Mfr_name: Panasonic - ECG; Mfr_part_number: ERJ-2RKF2001X; Package: 0402; Part_Number: 105A520014; Price @ 1: 0.10000; Price @ 10K: 0.00347; Price @ 1K: 0.00672; ProcessType: SMT; Tolerance: 1%; Vendor: DIGIKEY; Vendor Part#: P2.00KLCT-ND; Vendor_Part_No: P2.00KLCT-ND; eI Part#: 02_00229_02
R616 R619 = 10_R_0: RES 90.9K OHM 1/10W 1% 0402 SMD; Distributor_name: DIGIKEY; Distributor_part_number: P90.9KLCT-ND; EIC Part#: 02_00967_01; Manufacture: Panasonic - ECG; Manufacture Part Number: ERJ-2RKF9092X; Manufacture(English): Panasonic - ECG; Manufacture_Part_Number: ERJ-2RKF9092X; Manufacturer: Panasonic - ECG; Manufacturer_Part_No: ERJ-2RKF9092X; Mfg: Panasonic Electronic Components; Mfg Part#: 02_00967_01; Mfr_name: Panasonic - ECG; Mfr_part_number: ERJ-2RKF9092X; Package: 0402; Part_Number: 1000000180; Price @ 1: 0.10000; Price @ 10K: 0.00347; Price @ 1K: 0.00672; ProcessType: SMT; Tolerance: 1%; Vendor: DIGIKEY; Vendor_Part_No: P90.9KLCT-ND; eI Part#: 02_00019_01
R623 = 10_R_0: RES 2.2K OHM 1/10W 5% 0402 SMD; Alt Mfg: Yageo; Alt Mfg Part#: RC0402JR-072K2L; Distributor_name: DIGIKEY; Distributor_part_number: P2.2KJCT-ND; EIC Part#: 02_00024_01; Manufacture: Panasonic - ECG; Manufacture Part Number: ERJ-2GEJ222X; Manufacture(English): Panasonic - ECG; Manufacture_Part_Number: ERJ-2GEJ222X; Manufacturer: Panasonic - ECG; Manufacturer_Part_No: ERJ-2GEJ222X; Mfg Part#: 02_00024_01; Mfr_name: Panasonic - ECG; Mfr_part_number: ERJ-2GEJ222X; Oper. Temp. Range: -55C to 125C; Package: 0402; ProcessType: SMT; Remark: Alt part is 1/16W; RoHS: Yes; Specifications: RES 2.2K OHM 1/10W 5% 0402 SMD; Tolerance: 5%; Vendor: DIGIKEY; Vendor Part#: P2.2KJCT-ND; Vendor_Part_No: P2.2KJCT-ND; eI Part#: 02_00019_01
R624 = 10_R_0: RES 10K OHM 1/10W 1% 0402 SMD; Alt Mfg: Yageo; Alt Mfg Part#: RC0402FR-0710KL; Distributor_name: DIGIKEY; Distributor_part_number: P10.0KLCT-ND; EIC Part#: 02_00027_01; Manufacture: Panasonic - ECG; Manufacture Part Number: ERJ-2RKF1002X; Manufacture(English): Panasonic - ECG; Manufacture_Part_Number: ERJ-2RKF1002X; Manufacturer: Panasonic - ECG; Manufacturer_Part_No: ERJ-2RKF1002X; Mfg Part#: 02_00027_01; Mfr_name: Panasonic - ECG; Mfr_part_number: ERJ-2RKF1002X; Mounting Status: NU; Mounting_Status: NU; Oper. Temp. Range: -55C ~ 125C; Package: 0402; Price @ 1: 0.10000; Price @ 10K: 0.00347; Price @ 1K: 0.00672; ProcessType: SMT; Remark: Alt part is 1/16W; RoHS: Yes; Tolerance: 1%; Vendor: DIGIKEY; Vendor Part#: P10.0KLCT-ND; Vendor_Part_No: P10.0KLCT-ND; eI Part#: 02_00027_01
R626 = 10_R_0: RES 10K OHM 1/10W 1% 0402 SMD; Alt Mfg: Yageo; Alt Mfg Part#: RC0402FR-0710KL; Distributor_name: DIGIKEY; Distributor_part_number: P10.0KLCT-ND; EIC Part#: 02_00027_01; Manufacture: Panasonic - ECG; Manufacture Part Number: ERJ-2RKF1002X; Manufacture(English): Panasonic - ECG; Manufacture_Part_Number: ERJ-2RKF1002X; Manufacturer: Panasonic - ECG; Manufacturer_Part_No: ERJ-2RKF1002X; Mfg Part#: 02_00027_01; Mfr_name: Panasonic - ECG; Mfr_part_number: ERJ-2RKF1002X; Oper. Temp. Range: -55C ~ 125C; Package: 0402; Price @ 1: 0.10000; Price @ 10K: 0.00347; Price @ 1K: 0.00672; ProcessType: SMT; Remark: Alt part is 1/16W; RoHS: Yes; Tolerance: 1%; Vendor: DIGIKEY; Vendor Part#: P10.0KLCT-ND; Vendor_Part_No: P10.0KLCT-ND; eI Part#: 02_00027_01
TP40-TP45 TP47 TP49 TP52 TP53 TP55 TP56 TP58 = 00_TP28_0: TEST PAD TP; Advansus_Part_Number: 0030000003; Avalue_Part_Number: 0030000003; Distributor_name: NA; Distributor_part_number: NA; EIC Part#: NA; Manufacture: NA; Manufacture Part Number: NA; Manufacture(English): NA; Manufacture_Part_Number: NA; Manufacturer: NA; Manufacturer_Part_No: NA; Mfg: NA; Mfg Part#: NA; Mfr_name: NA; Mfr_part_number: NA; Part_Number: 0030000003; Price @ 1: NA; Price @ 10K: NA; Price @ 1K: NA; ProcessType: SMT; Vendor: NA; Vendor_Part_No: NA; eI Part#: NA
U17 = 141_TI_PCA9306DCUT_0: IC VOLT LEVEL TRANSLATOR US8; Distributor_name: DIGIKEY; Distributor_part_number: 296-17988-1-ND; EIC Part#: 01_00044_01; Manufacture: TI; Manufacture Part Number: PCA9306DCUR; Manufacture(English): TI; Manufacture_Part_Number: PCA9306DCUR; Manufacturer: TI; Manufacturer_Part_No: PCA9306DCUR; Mfg: TI; Mfg Part#: 01_00044_01; Mfr_name: TI; Mfr_part_number: PCA9306DCUR; Package: US8; Price @ 1: 0.94000; Price @ 10K: 0.32500; Price @ 1K: 0.33151; ProcessType: SMT; RoHS: Yes; Vendor: DIGIKEY; Vendor Part#: 296-17988-1-ND; Vendor_Part_No: 296-17988-1-ND; eI Part#: TBD
U25 = 141_TI_UCD9090_0: IC SEQUENCER/MONITOR 10CH 48VQFN; AVL_Part: AVL; Distributor_name: DIGIKEY; Distributor_part_number: 296-29403-1-ND; EIC Part#: 01_01118_01; Manufacture: TI; Manufacture(English): TI; Manufacturer: TI; Mfg: TI; Mfg Part#: 01_01118_01; Mfr_name: TI; Package: VQFN48; Part_Number: 1410022973-01; Price @ 1: 9.64000; Price @ 10K: 4.94888; Price @ 1K: 4.94888; ProcessType: SMT; RoHS: Yes; Vendor: DIGIKEY; Vendor Part#: 296-29403-1-ND; Vendor_Part_No: 296-29403-1-ND; eI Part#: TBD

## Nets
GND: C114.2 C117.2 C139.2 C142.2 C204.2 C530.2 C531.1 C594.2 C684.2 C685.1 C721.2 C731.2 C746.2 C750.2 C755.2 PMBUS1.5 Q3.2(GND) R212.1 R315.1 R320.1 R611.1 R613.1 R616.2 R619.1 R626.1 R635.1 R636.1 R637.1 R638.1 R666.1 R667.1 R669.2 R670.2 R671.1 R672.1 U17.1(GND) U25.32(DVSS) U25.49(THERMAL_PAD) U25.50(THERMAL_VIA1) U25.51(THERMAL_VIA2) U25.52(THERMAL_VIA3) U25.53(THERMAL_VIA4) U25.54(THERMAL_VIA5) U25.55(THERMAL_VIA6) U25.56(THERMAL_VIA7) U25.57(THERMAL_VIA8) U25.58(THERMAL_VIA9) U25.59(THERMAL_VIA10) U25.60(THERMAL_VIA11) U25.61(THERMAL_VIA12) U25.62(THERMAL_VIA13) U25.63(THERMAL_VIA14) U25.64(THERMAL_VIA15) U25.65(THERMAL_VIA16) U25.66(THERMAL_VIA17) U25.67(THERMAL_VIA18) U25.68(THERMAL_VIA19) U25.69(THERMAL_VIA20) U25.70(THERMAL_VIA21) U25.71(THERMAL_VIA22) U25.72(THERMAL_VIA23) U25.73(THERMAL_VIA24) U25.74(THERMAL_VIA25) U33.25(VDD_SEL) U33.55(GND) ; also on sheet 1 2 3 4 5 6 8 10 11 12 13 14 15 16 17 18 19 20 21 22 24 25 26 27 28 29 33 34 35 36 41 42 43 45 46 47
GND_3: C158.2 C160.2 U25.36(AVSS1) U25.47(AVSS2)
VCC0V75_EN: R215.2 ; also on sheet 19
VCC0V75_MON: R240.1 U25.45(MON8)
VCC0V85: R249.2 ; also on sheet 33 34
VCC0V85_EN: R269.2 ; also on sheet 34
VCC0V85_MON: R249.1 U25.2(MON2)
VCC1V5_EN: R254.2 ; also on sheet 35
VCC1V5_MON: R236.1 U25.42(MON7)
VCC1V8: C117.1 R156.1 R166.1 R231.2 U17.2(VREF1) ; also on sheet 2 6 8 11 19 21 22 25 26 27 29 33 34 36 41
VCC1V8_EN: R227.2 ; also on sheet 34
VCC1V8_MON: R231.1 U25.41(MON6)
VCC3_AUX_MON: R225.1 R613.2 U25.39(MON4)
VCC3V3_AUX: C204.1 C684.1 C685.2 Q3.4(VDD) R225.2 R279.2 R280.2 R281.2 R283.2 R316.2 R317.2 R318.1 R319.1 R321.2 R322.2 R668.2 R673.2 U33.24(VIN) ; also on sheet 2 4 6 8 11 12 13 16 18 19 22 25 26 27 28 29 33 35 45 47
VCC3V3_AUX_EN: R251.2 ; also on sheet 33
VCC3V3_MP: C139.1 C142.1 FB4.1 R213.1 R214.1 R268.1 R623.1 R624.1 U25.33(V33D) ; also on sheet 4 5 18 22 41
VCC5: R221.2 ; also on sheet 8 26 34
VCC5_MON: R221.1 R611.2 U25.38(MON3)
VCC5V_EN: R625.2 ; also on sheet 34
VDD33_EN: R255.2 ; also on sheet 25
VDD_DDR: R236.2 ; also on sheet 1 19 20 33 35
9090FPWM4: TP58.1 U25.13(FPWM4/GPIO8)
9090FPWM6: TP56.1 U25.15(FPWM6/GPIO10)
9090FPWM7: TP55.1 U25.16(FPWM7/GPIO11)
9090FPWM8: TP53.1 U25.17(FPWM8/GPIO12)
BMC_I2C1_SCL: R342.1 ; also on sheet 4 5 41 45 47
BMC_I2C1_SDA: R341.1 ; also on sheet 4 5 41 45 47
BPCAP: C530.1 C531.2 U25.35(BPCAP)
CVDD: R248.2 ; also on sheet 3 35 36
CVDD1: R228.2 ; also on sheet 34 36
CVDD1_EN: R239.2 ; also on sheet 34
CVDD1_MON: R228.1 U25.40(MON5)
CVDD_EN: R250.2 ; also on sheet 35
CVDD_MON: R248.1 U25.1(MON1)
DSP_PMBUS_EN: R173.2 ; also on sheet 5
EQ_D0_SW3: R266.1 ; also on sheet 45
EQ_D0_SW3_R: R266.2 R280.1 R636.2 U33.20(EQ_D0)
EQ_D1_SW3: R267.1 ; also on sheet 45
EQ_D1_SW3_R: R267.2 R281.1 R635.2 U33.19(EQ_D1)
FAN_PWM: R242.2 ; also on sheet 25
JTAG_TCK: TP44.1 U25.27(TCK/GPIO18)
JTAG_TDI: R214.2 TP42.1 U25.29(TDI/GPIO20)
JTAG_TDO: TP43.1 U25.28(TDO/GPIO19)
JTAG_TMS: R213.2 TP41.1 U25.30(TMS/GPIO21)
LM10011_VID1C: R166.2 U17.3(SCL1) ; also on sheet 25 35
LM10011_VID1S: R156.2 U17.4(SDA1) ; also on sheet 25 35
MAIN_POWER_GOOD: R217.2 ; also on sheet 5
MAIN_POWER_START: R223.1 ; also on sheet 5
MAIN_POWER_START_R: R223.2 TP52.1 U25.22(PWM1/GPI1)
PCIe0/SGMII2_RXN_SOC: U33.4(D_OUT0-) ; also on sheet 2
PCIe0/SGMII2_RXP_SOC: U33.3(D_OUT0+) ; also on sheet 2
PCIe0/SGMII2_TXN_SOC: C244.1 ; also on sheet 2
PCIe0/SGMII2_TXN_SOC_NET: C244.2 U33.11(D_IN0-)
PCIe0/SGMII2_TXP_SOC: C253.1 ; also on sheet 2
PCIe0/SGMII2_TXP_SOC_NET: C253.2 U33.10(D_IN0+)
PCIe0_RXN_AMC: C266.1 ; also on sheet 18
PCIe0_RXN_AMC_NET: C266.2 U33.44(S_INA0-)
PCIe0_RXP_AMC: C269.1 ; also on sheet 18
PCIe0_RXP_AMC_NET: C269.2 U33.45(S_INA0+)
PCIe0_TXN_AMC: U33.34(S_OUTA0-) ; also on sheet 18
PCIe0_TXP_AMC: U33.35(S_OUTA0+) ; also on sheet 18
PCIe1/SGMII3_RXN_SOC: U33.8(D_OUT1-) ; also on sheet 2
PCIe1/SGMII3_RXP_SOC: U33.7(D_OUT1+) ; also on sheet 2
PCIe1/SGMII3_TXN_SOC: C222.1 ; also on sheet 2
PCIe1/SGMII3_TXN_SOC_NET: C222.2 U33.16(D_IN1-)
PCIe1/SGMII3_TXP_SOC: C234.1 ; also on sheet 2
PCIe1/SGMII3_TXP_SOC_NET: C234.2 U33.15(D_IN1+)
PCIe1_RXN_AMC: C245.1 ; also on sheet 18
PCIe1_RXN_AMC_NET: C245.2 U33.39(S_INA1-)
PCIe1_RXP_AMC: C254.1 ; also on sheet 18
PCIe1_RXP_AMC_NET: C254.2 U33.40(S_INA1+)
PCIe1_TXN_AMC: U33.30(S_OUTA1-) ; also on sheet 18
PCIe1_TXP_AMC: U33.31(S_OUTA1+) ; also on sheet 18
PMBUS_ALERT: PMBUS1.3 R234.1 ; also on sheet 5 6 34 35
PMBUS_CLK: PMBUS1.1 R246.2 R623.2 U25.8(PMBUS_CLK) ; also on sheet 34 35
PMBUS_CTL: PMBUS1.4 R230.1 ; also on sheet 5 35
PMBUS_DAT: PMBUS1.2 R256.2 R268.2 U25.9(PMBUS_DATA) ; also on sheet 34 35
PW_SEQ_RSTz: C594.1 R624.2 R626.2 U25.3(~{RESET}) ; also on sheet 5
PW_SEQ_SCL: R246.1 U17.6(SCL2) ; also on sheet 4 26
PW_SEQ_SDA: R256.1 U17.5(SDA2) ; also on sheet 4 26
SERDES_SW3_SEL0_FPGA_3V3_EXP5: U33.23(SEL0) ; also on sheet 27
SERDES_SW3_SEL1_FPGA_3V3_EXP5: U33.26(SEL1/~{READ_E}N) ; also on sheet 27
SGMII2_RXN_AMC: C260.1 ; also on sheet 18
SGMII2_RXN_AMC_NET: C260.2 U33.42(S_INB0-)
SGMII2_RXP_AMC: C263.1 ; also on sheet 18
SGMII2_RXP_AMC_NET: C263.2 U33.43(S_INB0+)
SGMII2_TXN_AMC: U33.32(S_OUTB0-) ; also on sheet 18
SGMII2_TXP_AMC: U33.33(S_OUTB0+) ; also on sheet 18
SGMII3_RXN_AMC: C228.1 ; also on sheet 18
SGMII3_RXN_AMC_NET: C228.2 U33.37(S_INB1-)
SGMII3_RXP_AMC: C238.1 ; also on sheet 18
SGMII3_RXP_AMC_NET: C238.2 U33.38(S_INB1+)
SGMII3_TXN_AMC: U33.28(S_OUTB1-) ; also on sheet 18
SGMII3_TXP_AMC: U33.29(S_OUTB1+) ; also on sheet 18
SOC_POWER_GOOD: R216.2 ; also on sheet 5
SOC_POWER_START: R219.1 ; also on sheet 5
SOC_POWER_START_R: R219.2 TP49.1 U25.23(PWM2/GPI2)
SOC_TEMP1: Q3.3(VOUT) U25.48(MON10)
USB_VBUS_EN: R253.2 ; also on sheet 8
VPP1V8: R243.2 ; also on sheet 25 36
VPP1V8_MON: R243.1 U25.46(MON9)
VTT_DDR3A: R240.2 ; also on sheet 1 19
N17488718: C750.1 U33.41(VDD4)
N17488734: C731.1 U33.36(VDD3)
N17488746: C721.1 U33.14(VDD2)
N17488754: C746.1 U33.9(VDD1)
N17488766: C755.1 U33.51(VDD)
N17488813: R283.1 R637.2 U33.21(MODE)
N17488873: R279.1 R638.2 U33.22(INPUT_EN)
N17488901: R317.1 R671.2 U33.48(ENSMB)
N17488944: R315.2 R673.1 U33.46(EQ_S0/AD3)
N17488946: R316.1 R672.2 U33.47(EQ_S1/AD2)
N17488958: R322.1 R666.2 U33.54(DEM_D1/AD0)
N17488983: R321.1 R667.2 U33.53(DEM_D0/AD1)
N17489116: R320.2 R668.1 U33.52(RESET#)
N18350343: C158.1 C160.1 FB4.2 U25.34(V33A)
N18350632: R239.1 U25.18(GPIO13)
N18350757: R619.2 U25.43(PMBUS_ADDR1)
N18350764: R212.2 TP40.1 U25.31(~{TRST})
N18350788: R255.1 U25.12(FPWM3/GPIO7)
N18350790: R227.1 U25.21(GPIO14)
N18350837: R254.1 U25.11(FPWM2/GPIO6)
N18350934: R616.1 U25.44(PMBUS_ADDR0)
N18350938: R216.1 TP45.1 U25.25(GPIO16)
N18350952: R217.1 TP47.1 U25.24(GPIO15)
N18351082: R251.1 U25.7(GPIO4)
N18351175: R215.1 U25.26(GPIO17)
N18351402: R625.1 U25.6(GPIO3)
N18351412: R250.1 U25.4(GPIO1)
N18351416: R269.1 U25.5(GPIO2)
N18351477: R234.2 U25.19(PMBUS_ALERT)
N18351479: R230.2 U25.20(PMBUS_CNTRL)
N18351577: R242.1 U25.14(FPWM5/GPIO9)
N18436452: C114.1 R173.1 U17.7(VREF2) U17.8(EN)
N19280962: R253.1 U25.10(FPWM1/GPIO5)
N19311304: TP64.1 U33.27(~{ALL_DONE})
N19611190: R319.2 R342.2 R669.1 U33.50(DEM_S1/SCL)
N19611229: R318.2 R341.2 R670.1 U33.49(DEM_S0/SDA)

Not connected (* = marked no-connect by the designer): Q3 1(NC1)* 5(NC2)*; U25 37(MON11)*; U33 1(NC1)* 2(NC2)* 5(NC3)* 6(NC4)* 12(NC5)* 13(NC6)* 17(NC7)* 18(NC8)*

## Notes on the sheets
sheet 37
- SOC Temp, UCD9090, PMBus Pgm conn, VID Isolator for PMBus
- SOC Temp
- Close to SoC
- Note: make the connection between
  GND and GND_3 right between the
  decoupling caps for V33A and V33D
  with a shunt trace
- Power Sequencing
- POWER ENABLE
- POWER DETECT
- Slave I2C Address = 0x65
  ( Internal ADDR[7:5] = 0b110
- PMBus Head
- CN7 removed
- Layout Note: The decoupling caps should be kept as close to the pins as
  possible with short traces (there is an AGND pin at the corner of the
  device by the power/ref pins) connecting back to the device, preferably
  without using vias for best performance.
- PMBus Address Bins
- PMBus Address
- PMBus RESISTANCE  ( K ohm )
- VID Isolator for PMBus
- OPEN
- --
- 11
- 200
- 10
- 154
- 9
- 118
- 8
- 90.9
- 7
- 69.8
- 6
- 53.6
- 5
- 41.2
- 4
- 31.6
- SHORT
- --
sheet 38
- CLOCK DISTRIBUTION
sheet 39
- POWER DISTRIBUTION
sheet 40
- SGMII/PCIe Serdes switch
- Note: Place the capacitors close to VDD pins of the IC.
- AC coupling caps
- Note: Output is fully
  compatible with AC
  coupled CML inputs. FMC
  / AMC end should
  support CML input.
- TABLE FOR SERDES CONNECTIONS
- Lamarr
  Ballname
- Lamarr
  Direction
- Lamarr
  Ball
- Lamarr SOC Net
  name to switch
- Sw/SOC
- Switch
  Inputs
- Switch
  Outputs
- AMC PCIe conn
- AMC
  Pin
- AMC SGMII
  conn
- AMC
  Pin
- CSISC2_3_RXN0
- Diff In
- AJ22
- PCIe0/SGMII2_RXN_SOC
- Sw Out
- PCIe0_RXN_AMC or
  SGMII2_RXN_AMC
- -
- PCIe0_RXN_AMC
- 48
- SGMII2_RXN_AMC
- 15
- CSISC2_3_RXP0
- Diff In
- AJ21
- PCIe0/SGMII2_RXP_SOC
- Sw Out
- PCIe0_RXP_AMC or
  SGMII2_RXP_AMC
- -
- PCIe0_RXP_AMC
- 47
- SGMII2_RXP_AMC
- 14
- CSISC2_3_RXN1
- Diff In
- AK23
- PCIe1/SGMII3_RXN_SOC
- Sw Out
- PCIe1_RXN_AMC or
  SGMII3_RXN_AMC
- -
- PCIe1_RXN_AMC
- 63
- SGMII3_RXN_AMC
- 24
- CSISC2_3_RXP1
- Diff In
- AK22
- PCIe1/SGMII3_RXP_SOC
- Sw Out
- PCIe1_RXP_AMC or
  SGMII3_RXP_AMC
- -
- PCIe1_RXP_AMC
- 62
- SGMII3_RXP_AMC
- 23
- CSISC2_1_TXN0
- Diff Out
- AH20
- PCIe0/SGMII2_TXN_SOC
- Sw In
- -
- PCIe0_TXN_AMC or
  SGMII2_TXN_AMC
- PCIe0_TXN_AMC
- 45
- SGMII2_TXN_AMC
- 12
- CSISC2_1_TXP0
- Diff Out
- AH21
- PCIe0/SGMII2_TXP_SOC
- Sw In
- -
- PCIe0_TXP_AMC or
  SGMII2_TXP_AMC
- PCIe0_TXP_AMC
- 44
- SGMII2_TXP_AMC
- 11
- CSISC2_1_TXN1
- Diff Out
- AG21
- PCIe1/SGMII3_TXN_SOC
- Sw In
- -
- PCIe1_TXN_AMC or
  SGMII1_TXN_AMC
- PCIe1_TXN_AMC
- 60
- SGMII3_TXN_AMC
- 21
- CSISC2_1_TXP1
- Diff Out
- AG22
- PCIe1/SGMII3_TXP_SOC
- Sw In
- -
- PCIe1_TXP_AMC or
  SGMII3_TXP_AMC
- PCIe1_TXP_AMC
- 59
- SGMII3_TXP_AMC
- 20
